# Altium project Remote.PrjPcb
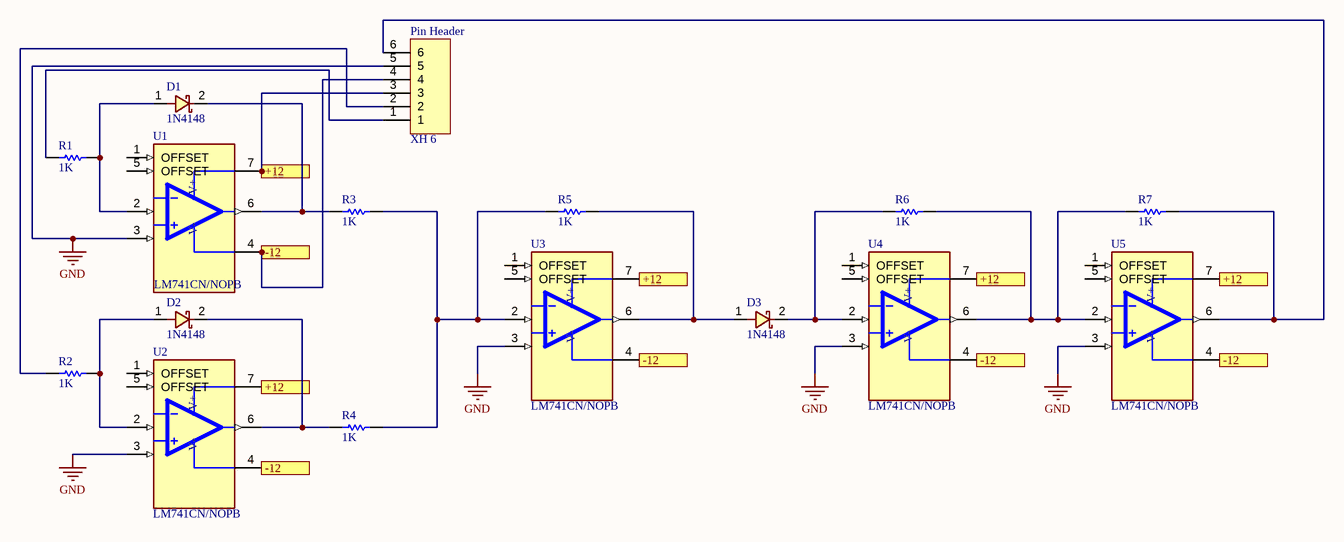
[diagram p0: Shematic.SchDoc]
1 sheet, 16 parts. Net scope: flat (ports and power ports of the same name join across sheets).
Board file: PCB.PcbDoc

## Sheet Shematic.SchDoc
size 431 x 279 mm; SheetNumber: 1; SheetTotal: 1

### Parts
D1  value 1N4148  [DO-35-]  (hidden comment: 1N4148 THD)
D2  value 1N4148  [DO-35-]  (hidden comment: 1N4148 THD)
D3  value 1N4148  [DO-35-]  (hidden comment: 1N4148 THD)
Pin_Header  XH 6  [XH 6 PIN]
R1  value 1K  [R1W_AX06]  (hidden comment: Resistor THD)
R2  value 1K  [R1W_AX06]  (hidden comment: Resistor THD)
R3  value 1K  [R1W_AX06]  (hidden comment: Resistor THD)
R4  value 1K  [R1W_AX06]  (hidden comment: Resistor THD)
R5  value 1K  [R1W_AX06]  (hidden comment: Resistor THD)
R6  value 1K  [R1W_AX06]  (hidden comment: Resistor THD)
R7  value 1K  [R1W_AX06]  (hidden comment: Resistor THD)
U1  LM741CN/NOPB  [DIP794W45P254L1016H508Q8]
U2  LM741CN/NOPB  [DIP794W45P254L1016H508Q8]
U3  LM741CN/NOPB  [DIP794W45P254L1016H508Q8]
U4  LM741CN/NOPB  [DIP794W45P254L1016H508Q8]
U5  LM741CN/NOPB  [DIP794W45P254L1016H508Q8]

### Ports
+12 (see Shematic[4B], Shematic[5B], Shematic[6B], Shematic[7B]), +12 (see Shematic[4B], Shematic[5B], Shematic[7B]), +12 (see Shematic[4B], Shematic[6B], Shematic[7B]), +12 (see Shematic[5B], Shematic[6B], Shematic[7B]), -12 (see Shematic[4B], Shematic[5B], Shematic[6B], Shematic[7A]), -12 (see Shematic[4B], Shematic[5B], Shematic[6B], Shematic[7B]), -12 (see Shematic[4B], Shematic[5B], Shematic[7A], Shematic[7B]), -12 (see Shematic[4B], Shematic[6B], Shematic[7A], Shematic[7B]), -12 (see Shematic[5B], Shematic[6B], Shematic[7A], Shematic[7B])

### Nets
GND: Pin_Header.5 U1.3(NON-INV_INPUT) U2.3(NON-INV_INPUT) U3.3(NON-INV_INPUT) U4.3(NON-INV_INPUT) U5.3(NON-INV_INPUT)
NetD1_1: D1.1 R1.2 U1.2(INV_INPUT)
NetD1_2: D1.2 R3.1 U1.6(OUTPUT)
NetD2_1: D2.1 R2.2 U2.2(INV_INPUT)
NetD2_2: D2.2 R4.1 U2.6(OUTPUT)
NetD3_1: D3.1 R5.2 U3.6(OUTPUT)
NetD3_2: D3.2 R6.1 U4.2(INV_INPUT)
NetPin_Header_1: Pin_Header.1 R1.1
NetPin_Header_2: Pin_Header.2 R2.1
NetPin_Header_3: Pin_Header.3 U1.7(V+) U2.7(V+) U3.7(V+) U4.7(V+) U5.7(V+) ; port +12
NetPin_Header_4: Pin_Header.4 U1.4(V-) U2.4(V-) U3.4(V-) U4.4(V-) U5.4(V-) ; port -12
NetPin_Header_6: Pin_Header.6 R7.2 U5.6(OUTPUT)
NetR3_2: R3.2 R4.2 R5.1 U3.2(INV_INPUT)
NetR6_2: R6.2 R7.1 U4.6(OUTPUT) U5.2(INV_INPUT)

Not connected (* = marked no-connect by the designer): U1 1(OFFSET) 5(OFFSET); U2 1(OFFSET) 5(OFFSET); U3 1(OFFSET) 5(OFFSET); U4 1(OFFSET) 5(OFFSET); U5 1(OFFSET) 5(OFFSET)

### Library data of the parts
D1-D3 = 1N4148 THD: High Conductance Fast Diode
Pin_Header = Conector XH 6 Pin
U1-U5 = LM741CN/NOPB: Ù…Ø¯Ø§Ø± ÛŒÚ©Ù¾Ø§Ø±Ú†Ù‡ Ø¢Ù…Ù¾Ø± Ø¹Ù…Ù„ÛŒØ§ØªÛŒ ØªÚ© Ù…Ù†Ø¸ÙˆØ±Ù‡ Ø¹Ù…ÙˆÙ…ÛŒ Ø´ÛŒØ¨ 8 Ø³Ø±Ø¨; MF: Texas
